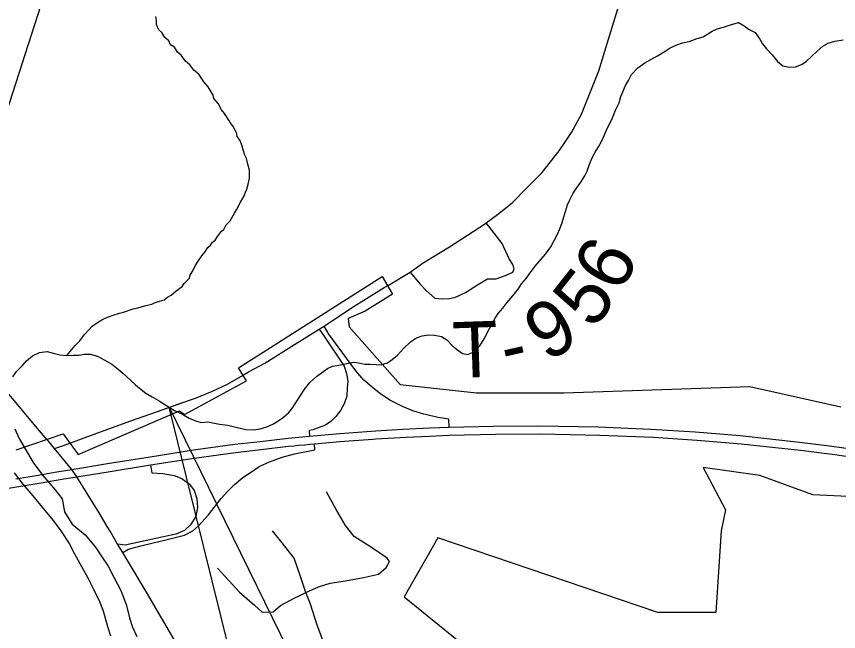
# Model space of a CAD drawing. Extents: x 0 to 34, y 0 to 22.
# Drawn here: x 5.409 to 6.245, y 17.533 to 18.159 of the extents above; entities that cross this region are included whole.
import ezdxf

# ---------------------------------------------------------------- set-up
doc = ezdxf.new("R2010")
doc.units = 0
for name, color, linetype in [('GM_X_City_Street', 7, 'Continuous'), ('GM_X_Corporation', 7, 'Continuous'), ('GM_X_Interchange_Ramps', 7, 'Continuous'), ('GM_X_Major_River', 7, 'Continuous'), ('GM_X_Minor_River', 7, 'Continuous'), ('GM_X_State_Route', 7, 'Continuous'), ('GM_X_Township_Road', 7, 'Continuous'), ('GM_X_Township_Road_Text', 7, 'Continuous'), ('SH_Text', 7, 'Continuous')]:
    doc.layers.add(name, color=color, linetype=linetype)

msp = doc.modelspace()

# ---------------------------------------------------------------- linework, layer by layer
at = {"layer": 'GM_X_City_Street'}
for points in [[(5.61297, 17.59719), (5.63544, 17.57303), (5.65079, 17.55955), (5.65832, 17.55266), (5.6696, 17.55297), (5.67712, 17.55924), (5.69091, 17.56676), (5.69627, 17.56931), (5.70275, 17.57261), (5.71563, 17.57821), (5.72769, 17.58195), (5.74338, 17.58458), (5.76163, 17.58775), (5.77693, 17.59129), (5.78457, 17.59787), (5.78787, 17.60423), (5.78552, 17.60765), (5.76963, 17.61835), (5.75198, 17.62954), (5.74315, 17.64072), (5.73385, 17.65708), (5.72408, 17.6752)], [(5.8488, 17.41184), (5.81062, 17.44657), (5.75883, 17.48462), (5.73764, 17.50366), (5.72942, 17.50952), (5.72813, 17.51087), (5.72275, 17.51649), (5.71417, 17.54019), (5.70779, 17.56081), (5.70275, 17.57261), (5.69749, 17.58901), (5.69091, 17.6075), (5.67882, 17.62326), (5.66885, 17.63523)]]:
    msp.add_lwpolyline(points, dxfattribs=at)
at = {"layer": 'GM_X_Corporation'}
for points in [[(5.3549, 18.32564), (5.47199, 18.28501), (5.42634, 18.18738), (5.4363, 18.18011), (5.32143, 17.82351)], [(5.40811, 17.71787), (5.45592, 17.73411), (5.47139, 17.7131), (5.57426, 17.75753), (5.57931, 17.75371), (5.64271, 17.78792), (5.63442, 17.80134), (5.78045, 17.89434), (5.7911, 17.87625), (5.76333, 17.85895), (5.74599, 17.85149), (5.74709, 17.84282), (5.7987, 17.78412), (5.87656, 17.77592), (5.96536, 17.77591), (6.15451, 17.78222), (6.24725, 17.76138)], [(6.27565, 17.66936), (6.2187, 17.6721), (6.16481, 17.69177), (6.10694, 17.69972), (6.12993, 17.65677), (6.12532, 17.63538), (6.12001, 17.55215), (6.06101, 17.55216), (5.83721, 17.62838), (5.83131, 17.61805), (5.80282, 17.56817), (5.9288, 17.4662)]]:
    msp.add_lwpolyline(points, dxfattribs=at)
at = {"layer": 'GM_X_Interchange_Ramps'}
for points in [[(5.71629, 17.84066), (5.72187, 17.8327), (5.74173, 17.80304), (5.74435, 17.79549), (5.74566, 17.78762), (5.74501, 17.7804), (5.74468, 17.77252), (5.74173, 17.76465), (5.73812, 17.75776), (5.73353, 17.75153), (5.72828, 17.74661), (5.72303, 17.743), (5.71647, 17.74037), (5.70991, 17.73807), (5.70614, 17.73737), (5.70652, 17.7318)], [(5.84853, 17.74083), (5.84831, 17.74898), (5.83754, 17.75077), (5.82302, 17.75402), (5.8117, 17.75761), (5.80133, 17.76176), (5.7891, 17.76809), (5.77935, 17.77432), (5.77032, 17.78138), (5.76202, 17.78884), (5.75361, 17.79803), (5.72623, 17.8356), (5.72155, 17.84372)], [(5.51662, 17.61345), (5.52236, 17.61671), (5.53509, 17.61997), (5.54756, 17.62324), (5.55904, 17.62587), (5.56987, 17.6285), (5.57937, 17.63079), (5.58791, 17.63539), (5.59381, 17.64031), (5.60397, 17.65179), (5.61644, 17.66787), (5.62365, 17.67574), (5.63021, 17.68263), (5.63874, 17.68952), (5.64759, 17.69542), (5.65547, 17.70067), (5.66596, 17.7056), (5.67876, 17.71019), (5.69122, 17.7138), (5.70532, 17.71643), (5.71205, 17.71765), (5.71186, 17.72399)], [(5.54505, 17.70252), (5.5462, 17.6944), (5.5576, 17.69357), (5.56897, 17.69172), (5.57685, 17.68847), (5.58451, 17.68267), (5.58915, 17.6764), (5.59216, 17.66828), (5.59286, 17.659), (5.591, 17.64995), (5.58567, 17.64136), (5.5794, 17.63557), (5.57059, 17.63209), (5.55807, 17.6293), (5.51909, 17.62072), (5.51135, 17.62172)]]:
    msp.add_lwpolyline(points, dxfattribs=at)
at = {"layer": 'GM_X_Major_River'}
for points in [[(5.40683, 17.73927), (5.41122, 17.72932), (5.41973, 17.71473), (5.42564, 17.70475), (5.43531, 17.69166), (5.44761, 17.67739), (5.45505, 17.66777), (5.4575, 17.6548), (5.46527, 17.64213), (5.4784, 17.63127), (5.48883, 17.61855)], [(5.4061, 17.69443), (5.41503, 17.68288), (5.42509, 17.67093), (5.4359, 17.65782), (5.44596, 17.64587), (5.45377, 17.63548), (5.4623, 17.62242), (5.46745, 17.61207), (5.47484, 17.59902), (5.48111, 17.58751), (5.487, 17.57601), (5.49287, 17.56337), (5.4969, 17.5538), (5.5012, 17.53815), (5.50409, 17.5286)], [(5.48883, 17.61855), (5.49551, 17.60894), (5.50181, 17.59933), (5.50771, 17.58821), (5.51508, 17.57402), (5.52054, 17.55949), (5.52338, 17.5469), (5.52664, 17.53734), (5.53105, 17.52777)]]:
    msp.add_lwpolyline(points, dxfattribs=at)
at = {"layer": 'GM_X_Minor_River'}
for points in [[(5.45984, 17.81371), (5.46824, 17.82381), (5.47288, 17.82867), (5.47755, 17.83467), (5.48258, 17.84029), (5.48568, 17.84365), (5.49184, 17.84811), (5.49529, 17.84995), (5.50105, 17.85289), (5.50678, 17.85469), (5.51328, 17.85686), (5.51748, 17.85793), (5.52742, 17.86118), (5.532, 17.86224), (5.54002, 17.86476), (5.54613, 17.86617), (5.54881, 17.86726), (5.55416, 17.86907), (5.55875, 17.87051), (5.56222, 17.87311), (5.56605, 17.87533), (5.57107, 17.87942), (5.57722, 17.88388), (5.57918, 17.88689), (5.58459, 17.8925), (5.5854, 17.89552), (5.58736, 17.89891), (5.5909, 17.90608), (5.59325, 17.90984), (5.59714, 17.91509), (5.60024, 17.91884), (5.60337, 17.92373), (5.60607, 17.92597), (5.60802, 17.92897), (5.61071, 17.93121), (5.61306, 17.93497), (5.61695, 17.94022), (5.61964, 17.94208), (5.622, 17.9466), (5.62587, 17.95072), (5.63019, 17.95863), (5.63252, 17.96201), (5.63646, 17.96993), (5.63998, 17.97557), (5.64157, 17.98011), (5.64276, 17.98313), (5.64437, 17.98804), (5.64561, 17.99411), (5.64575, 18.00247), (5.64395, 18.00859), (5.64253, 18.01432), (5.64069, 18.01777), (5.63926, 18.02312), (5.63818, 18.02695), (5.636, 18.03269), (5.63302, 18.03654), (5.63269, 18.03921), (5.62939, 18.0465), (5.62604, 18.05074), (5.62456, 18.05343), (5.62011, 18.05997), (5.61713, 18.06383), (5.61382, 18.07035), (5.60934, 18.07537), (5.60864, 18.07881), (5.60346, 18.08727), (5.59898, 18.09229), (5.59417, 18.09998), (5.58892, 18.10426), (5.58483, 18.10965), (5.58033, 18.11316), (5.57625, 18.11931), (5.5725, 18.12242), (5.56916, 18.12743), (5.5654, 18.12977), (5.56357, 18.13399), (5.55945, 18.13748), (5.55649, 18.14248), (5.55349, 18.1452), (5.55202, 18.14788), (5.55092, 18.15057), (5.551, 18.15475), (5.5503, 18.15894)], [(5.96376, 17.94901), (5.96536, 17.95506), (5.96696, 17.96035), (5.96895, 17.96715), (5.9713, 17.97205), (5.97482, 17.97883), (5.97831, 17.9841), (5.98258, 17.99011), (5.98685, 17.9965), (5.98919, 18.0014), (5.99118, 18.00744), (5.99394, 18.01423), (5.99707, 18.02064), (6.00057, 18.02629), (6.00368, 18.03155), (6.00682, 18.03834), (6.00918, 18.044), (6.01231, 18.05041), (6.01466, 18.05568), (6.01781, 18.06361), (6.02171, 18.07077), (6.02332, 18.0772), (6.02529, 18.0821), (6.02804, 18.08851), (6.03116, 18.09378), (6.03428, 18.09981), (6.04046, 18.10655), (6.04775, 18.11176), (6.05388, 18.11509), (6.06077, 18.11878), (6.06844, 18.1236), (6.07343, 18.12695), (6.08031, 18.12988), (6.08604, 18.13207), (6.0929, 18.13349), (6.10092, 18.13641), (6.10703, 18.13822), (6.11623, 18.14378), (6.1212, 18.14636), (6.12768, 18.14779), (6.13494, 18.15034), (6.14295, 18.1525), (6.14861, 18.14938), (6.15387, 18.1455), (6.15991, 18.14238), (6.16476, 18.13585), (6.16735, 18.13088), (6.17146, 18.12588), (6.17707, 18.11973), (6.18268, 18.11281), (6.18794, 18.10856), (6.19476, 18.10732), (6.20084, 18.10761), (6.20696, 18.1098), (6.21194, 18.11314), (6.21772, 18.11837), (6.22311, 18.12361), (6.22888, 18.12846), (6.23425, 18.13179), (6.24111, 18.13359), (6.24949, 18.13498)], [(5.40482, 17.79212), (5.40869, 17.79738), (5.41448, 17.80337), (5.41872, 17.80824), (5.42488, 17.81346), (5.43214, 17.81677), (5.43976, 17.8178), (5.44733, 17.81579), (5.45263, 17.81457), (5.45984, 17.81371), (5.46669, 17.81399), (5.47239, 17.81428), (5.47734, 17.81497), (5.48342, 17.81526), (5.491, 17.81325), (5.49854, 17.80896), (5.5057, 17.80506), (5.51209, 17.80003), (5.51697, 17.7954), (5.5241, 17.78885), (5.52973, 17.78383), (5.53536, 17.77919), (5.54025, 17.77532), (5.54666, 17.77181), (5.55382, 17.76753), (5.56211, 17.7621), (5.56926, 17.75782), (5.57682, 17.75429), (5.58436, 17.75), (5.59153, 17.74686), (5.59684, 17.74564), (5.60331, 17.74631), (5.61013, 17.74507), (5.61505, 17.74385), (5.6234, 17.74297), (5.63173, 17.74095), (5.64196, 17.73852), (5.64993, 17.73803), (5.65641, 17.73907), (5.66328, 17.74125), (5.6694, 17.74381), (5.67438, 17.74678), (5.68014, 17.75087), (5.68552, 17.75572), (5.68978, 17.76097), (5.69755, 17.773), (5.70182, 17.77977), (5.70685, 17.78615), (5.71378, 17.7925), (5.71877, 17.79623), (5.72492, 17.80069), (5.72989, 17.8029), (5.73484, 17.80358), (5.7398, 17.80465), (5.74628, 17.80607), (5.75161, 17.80713), (5.75692, 17.80629), (5.76298, 17.80507), (5.7683, 17.80499), (5.77437, 17.80452), (5.77931, 17.80444), (5.7858, 17.80625), (5.79079, 17.80959), (5.79617, 17.81407), (5.80235, 17.82081), (5.80928, 17.82754), (5.81542, 17.83162), (5.82115, 17.83382), (5.82763, 17.83486), (5.8337, 17.83439), (5.8409, 17.83314), (5.84617, 17.82965), (5.85142, 17.82426), (5.8563, 17.82039), (5.86232, 17.81575), (5.86763, 17.81491), (5.87375, 17.81748), (5.87991, 17.82346), (5.88419, 17.83061), (5.88966, 17.84116), (5.89278, 17.8468), (5.89551, 17.8517), (5.89862, 17.85659), (5.90325, 17.86183), (5.90751, 17.86747), (5.91331, 17.87459), (5.91873, 17.88135), (5.92222, 17.88661), (5.92686, 17.89223), (5.93112, 17.89786), (5.93615, 17.90462), (5.94233, 17.91174), (5.94659, 17.917), (5.95201, 17.92451), (5.95903, 17.93731), (5.96139, 17.94259), (5.96376, 17.94901)]]:
    msp.add_lwpolyline(points, dxfattribs=at)
at = {"layer": 'GM_X_State_Route'}
for p, q in [((5.55874, 17.75925), (5.56718, 17.76223)), ((5.44733, 17.71913), (5.44115, 17.72655)), ((5.44733, 17.71913), (5.45647, 17.72235)), ((5.51662, 17.61345), (5.51135, 17.62172))]:
    msp.add_line(p, q, dxfattribs=at)
for points in [[(5.99764, 18.09513), (6.00093, 18.1035), (6.01091, 18.13568), (6.02012, 18.16674), (6.03019, 18.19927), (6.04054, 18.22638), (6.05132, 18.25276), (6.06351, 18.27063), (6.08855, 18.29736), (6.11114, 18.3143), (6.13656, 18.33012), (6.17383, 18.34894), (6.20979, 18.36626), (6.22899, 18.37436), (6.22994, 18.37483)], [(5.78255, 17.88281), (5.78596, 17.88484), (5.80893, 17.89848), (5.8224, 17.908), (5.84899, 17.92445), (5.88559, 17.94819), (5.88648, 17.94885), (5.89784, 17.95723), (5.91281, 17.9691), (5.92852, 17.98505), (5.94311, 17.99965), (5.96042, 18.02215), (5.9671, 18.03168), (5.97329, 18.04071), (5.98343, 18.0595), (5.99295, 18.08325), (5.99691, 18.09327), (5.99764, 18.09513)], [(5.72155, 17.84372), (5.74931, 17.86237), (5.77998, 17.88129), (5.78255, 17.88281)], [(5.44115, 17.72655), (5.43991, 17.72803), (5.43002, 17.73961), (5.40819, 17.76571), (5.38976, 17.78716), (5.37768, 17.80093), (5.3674, 17.81172), (5.35537, 17.82394), (5.34384, 17.83513), (5.32996, 17.84782), (5.32475, 17.85232)], [(5.69127, 17.82495), (5.71629, 17.84066), (5.72155, 17.84372)], [(5.64063, 17.79467), (5.64472, 17.79702), (5.66124, 17.8061), (5.69127, 17.82495)], [(5.56718, 17.76223), (5.57281, 17.76421), (5.5905, 17.77049), (5.60795, 17.77748), (5.62331, 17.78469), (5.639, 17.79373), (5.64063, 17.79467)], [(5.45647, 17.72235), (5.46287, 17.7246), (5.48668, 17.7333), (5.52497, 17.74736), (5.55874, 17.75925)], [(5.40797, 17.68835), (5.42864, 17.69173), (5.44977, 17.69526), (5.46499, 17.69769), (5.50115, 17.70371), (5.54449, 17.71078), (5.58867, 17.71767), (5.63072, 17.72345), (5.65651, 17.72642), (5.68482, 17.72973), (5.70652, 17.7318), (5.73764, 17.73439), (5.77397, 17.73711), (5.80144, 17.73888), (5.82892, 17.74011), (5.84853, 17.74083), (5.89362, 17.74191), (5.93948, 17.74207), (6.00025, 17.74118), (6.05394, 17.73896), (6.09894, 17.73607), (6.14485, 17.7322), (6.20518, 17.72567), (6.23554, 17.72188), (6.26469, 17.71779)], [(5.37649, 17.67495), (5.41287, 17.68092), (5.43355, 17.6843), (5.45467, 17.68783), (5.46989, 17.69026), (5.50171, 17.69545), (5.54505, 17.70252), (5.58923, 17.70941), (5.63128, 17.71518), (5.65707, 17.71815), (5.68538, 17.72146), (5.69105, 17.72199), (5.69559, 17.72242), (5.70185, 17.72303), (5.70708, 17.72354), (5.71186, 17.72399), (5.73735, 17.72617), (5.7712, 17.72873)], [(5.7712, 17.72873), (5.77419, 17.72896), (5.80508, 17.73064), (5.82863, 17.73176), (5.84876, 17.73268), (5.89585, 17.73384), (5.94155, 17.73401), (6.00198, 17.73283), (6.05642, 17.73053), (6.10083, 17.72756), (6.14579, 17.72375), (6.20595, 17.71747), (6.2411, 17.71287), (6.27295, 17.70822), (6.3192, 17.70076), (6.38581, 17.68775), (6.4139, 17.6812)], [(5.50095, 17.63978), (5.49263, 17.65376), (5.48062, 17.6733), (5.46989, 17.69026), (5.46499, 17.69769), (5.44733, 17.71913)], [(5.51135, 17.62172), (5.50373, 17.63512), (5.50095, 17.63978)], [(5.62949, 17.37747), (5.63058, 17.38688), (5.63043, 17.39831), (5.62698, 17.4168), (5.624, 17.42518), (5.62251, 17.42937), (5.62102, 17.43357), (5.61856, 17.43866), (5.61609, 17.44375), (5.61115, 17.45394), (5.5958, 17.47995), (5.5712, 17.52053), (5.54095, 17.57303), (5.52212, 17.60429), (5.51662, 17.61345)]]:
    msp.add_lwpolyline(points, dxfattribs=at)
at = {"layer": 'GM_X_Township_Road'}
msp.add_lwpolyline([(5.80893, 17.89848), (5.81877, 17.88683), (5.82545, 17.87994), (5.83402, 17.87221), (5.84154, 17.87159), (5.84906, 17.8718), (5.85511, 17.87326), (5.86514, 17.87785), (5.87767, 17.88558), (5.8877, 17.89164), (5.89636, 17.8918), (5.90608, 17.89519), (5.91341, 17.89866), (5.91485, 17.90208), (5.91339, 17.90626), (5.90963, 17.91232), (5.90253, 17.92777), (5.88648, 17.94885)], dxfattribs=at)
at = {"layer": 'SH_Text'}
for p, q in [((5.54523, 17.75451), (5.57891, 17.7664)), ((5.84524, 16.62684), (5.56385, 17.76105)), ((5.56385, 17.76105), (5.84524, 17.18665))]:
    msp.add_line(p, q, dxfattribs=at)

# ---------------------------------------------------------------- texts
at = {"layer": 'GM_X_Township_Road_Text'}
for s, rotation, p in [('6', 62.05754, (6.0225, 17.87591)), ('5', 51.77822, (5.99478, 17.83911)), ('9', 31.03097, (5.94806, 17.80631)), ('T', 2.00181, (5.85306, 17.79082)), ('-', 12.81303, (5.90711, 17.79381))]:
    msp.add_text(s, height=0.05682, rotation=rotation, dxfattribs=at).set_placement(p)

doc.saveas('drawing.dxf')
